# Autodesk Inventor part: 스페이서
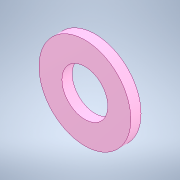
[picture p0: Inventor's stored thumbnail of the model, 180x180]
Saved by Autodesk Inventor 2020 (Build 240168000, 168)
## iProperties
Created: 2024-04
Part Number: 스페이서
Material: 강철, 연강
Document SubType Name: Modeling
Designer: oem
Density: 7.86 g/cm^3
Appearance: 기본값
Author: jhkim
Sending System: Autodesk Inventor 2025
Preprocessor: ST-DEVELOPER v20
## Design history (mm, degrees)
feature "솔리드1"
node "솔리드2"
